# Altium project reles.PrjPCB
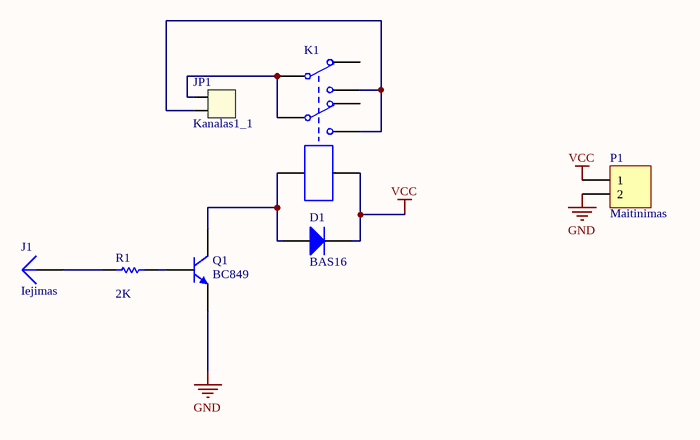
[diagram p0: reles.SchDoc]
1 sheet, 7 parts. Net scope: global (net labels, ports and power ports of the same name join across sheets).
Board file: reles.PcbDoc

## Sheet reles.SchDoc
size A4

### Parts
D1  BAS16  [SOT-23]
J1  Iejimas  [PIN1]
JP1  Kanalas1_1  [JP jungties Foot_print]
K1  Relay-DPDT  [rele]  (value not drawn)
P1  Maitinimas  [HDR1X2]
Q1  BC849  [318-08]
R1  value 2K  [1005[0402]]  (hidden comment: Res Semi)

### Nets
GND: P1.2 Q1.2(E)
VCC: D1.3(K) K1.8 P1.1
NetD1_1: D1.1(A) K1.7 Q1.3(C)
NetJ1_1: J1.1 R1.1
NetJP1_1: JP1.1 K1.1 K1.4
NetJP1_2: JP1.2 K1.3 K1.6
NetQ1_1: Q1.1(B) R1.2

Not connected (* = marked no-connect by the designer): K1 2 5

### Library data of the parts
D1 = Diode BAS16: Silicon Switching Diode for High-Speed Switching; Note: Pin 2 is not connected and not drawn.
J1 = Plug
JP1 = TB-002: Lituojama jungtis prisukama varzteliais. 5.08mm. skyle 3.5mm
K1 = Relay-DPDT: Dual-Pole Dual-Throw Relay
P1 = Header 2: Header, 2-Pin
Q1 = BC849ALT1: General Purpose Transistor NPN Silicon
R1 = Res Semi: Semiconductor Resistor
